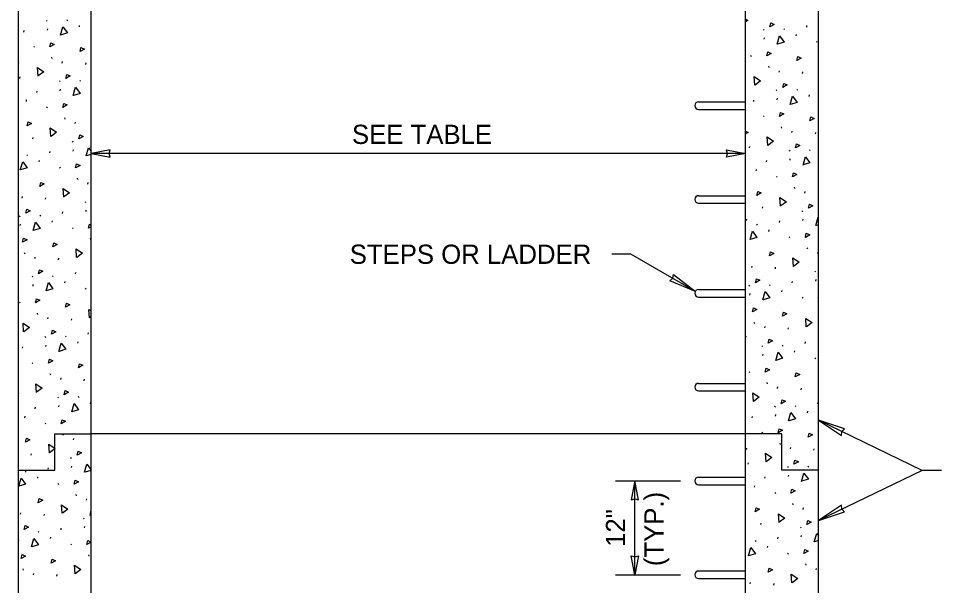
# Model space of a CAD drawing. Extents: x 99862 to 103151, y 100000 to 102076.
# Drawn here: x 100604 to 101372, y 101023 to 101495 of the extents above; entities that cross this region are included whole.
import ezdxf

# ---------------------------------------------------------------- set-up
doc = ezdxf.new("R2010")
doc.units = 0
for name, color, linetype in [('Level 15', 7, 'Continuous'), ('Level 16', 7, 'Continuous'), ('Level 17', 7, 'Continuous'), ('Level 18', 7, 'Continuous'), ('Level 20', 7, 'Continuous')]:
    doc.layers.add(name, color=color, linetype=linetype)

msp = doc.modelspace()

# ---------------------------------------------------------------- linework, layer by layer
at = {"layer": 'Level 15'}
for p, q in [((101209.03, 101382.81), (100664.59, 101382.81)), ((101113.68, 101299.02), (101097.68, 101299.02)), ((101167.26, 101268.08), (101113.68, 101299.02)), ((101355.84, 101119.04), (101269.59, 101160.87)), ((101355.84, 101119.04), (101269.59, 101077.42)), ((101372.07, 101119.14), (101356.07, 101119.14)), ((101100.85, 101110.31), (101154.85, 101110.31)), ((101116.85, 101032.25), (101116.85, 101110.33)), ((101100.85, 101032.23), (101154.85, 101032.23))]:
    msp.add_line(p, q, dxfattribs=at)
for points in [[(100664.59, 101382.81), (100680.32, 101379.73), (100679.59, 101382.81), (100680.32, 101385.89)], [(101209.03, 101382.81), (101193.3, 101379.73), (101194.03, 101382.81), (101193.3, 101385.89)], [(101167.26, 101268.08), (101146, 101276.91), (101148.41, 101278.97), (101148.98, 101282.08)], [(101269.59, 101160.87), (101288.83, 101148.22), (101289.18, 101151.37), (101291.44, 101153.59)], [(101116.85, 101110.33), (101113.76, 101094.6), (101116.85, 101095.33), (101119.93, 101094.6)], [(101269.59, 101077.42), (101291.45, 101084.65), (101289.2, 101086.88), (101288.86, 101090.03)], [(101116.85, 101032.25), (101113.76, 101047.98), (101116.85, 101047.25), (101119.93, 101047.98)]]:
    msp.add_lwpolyline(points, close=True, dxfattribs=at)
at = {"layer": 'Level 16'}
for p, q in [((100627.44, 101493.7), (100628.08, 101493.08)), ((100644.48, 101494.09), (100645.12, 101493.46)), ((100608.71, 101484), (100608.96, 101485.2)), ((100628.22, 101485.49), (100628.48, 101486.69)), ((100654.77, 101488.21), (100655.02, 101489.41)), ((101223.82, 101486.19), (101224.46, 101485.56)), ((101240.86, 101486.58), (101241.5, 101485.95)), ((101259.87, 101488.13), (101260.12, 101489.33)), ((101224.6, 101477.98), (101224.86, 101479.18)), ((101251.15, 101480.7), (101251.4, 101481.9)), ((100616.85, 101472.02), (100617.49, 101471.39)), ((101268.01, 101476.15), (101268.65, 101475.52)), ((100631.62, 101462.97), (100631.98, 101461.9)), ((101213.23, 101464.51), (101213.87, 101463.88)), ((100640.58, 101458.12), (100640.83, 101459.32)), ((100660.12, 101457.07), (100660.38, 101458.27)), ((101228, 101455.46), (101228.36, 101454.39)), ((100605.34, 101445.42), (100605.6, 101446.62)), ((101236.96, 101450.61), (101237.21, 101451.81)), ((101256.5, 101449.56), (101256.76, 101450.75)), ((100638.14, 101443.37), (100638.78, 101442.75)), ((100655.17, 101443.76), (100655.81, 101443.13)), ((100619.41, 101433.67), (100619.66, 101434.87)), ((100638.92, 101435.16), (100639.17, 101436.36)), ((101234.52, 101435.86), (101235.16, 101435.24)), ((101251.56, 101436.25), (101252.2, 101435.62)), ((101261.85, 101430.37), (101262.1, 101431.57)), ((100610.69, 101426.24), (100610.94, 101427.44)), ((101215.79, 101426.16), (101216.04, 101427.36)), ((101235.3, 101427.65), (101235.56, 101428.85)), ((100627.55, 101421.69), (100628.19, 101421.06)), ((100642.32, 101412.64), (100642.67, 101411.57)), ((100651.27, 101407.79), (100651.53, 101408.99)), ((101223.93, 101414.18), (101224.57, 101413.55)), ((101238.7, 101405.13), (101239.06, 101404.06)), ((101247.66, 101400.28), (101247.91, 101401.48)), ((100616.04, 101395.1), (100616.3, 101396.29)), ((100648.84, 101393.04), (100649.47, 101392.42)), ((101267.2, 101399.23), (101267.45, 101400.43)), ((100649.61, 101384.84), (100649.87, 101386.04)), ((101212.42, 101387.58), (101212.68, 101388.78)), ((101245.22, 101385.53), (101245.86, 101384.91)), ((101262.25, 101385.92), (101262.89, 101385.3)), ((100611.09, 101381.79), (100611.73, 101381.16)), ((100630.1, 101383.34), (100630.36, 101384.54)), ((101246, 101377.32), (101246.25, 101378.52)), ((100621.39, 101375.91), (100621.64, 101377.11)), ((100638.24, 101371.36), (100638.88, 101370.74)), ((101226.48, 101375.83), (101226.74, 101377.03)), ((100653.02, 101362.31), (100653.37, 101361.24)), ((101217.77, 101368.4), (101218.02, 101369.6)), ((101234.63, 101363.85), (101235.27, 101363.23)), ((100661.97, 101357.47), (100662.22, 101358.67)), ((101249.4, 101354.8), (101249.75, 101353.73)), ((100607.2, 101345.82), (100607.45, 101347.02)), ((101258.35, 101349.96), (101258.61, 101351.15)), ((100626.74, 101344.77), (100626.99, 101345.97)), ((100659.53, 101342.72), (100660.17, 101342.09)), ((100621.79, 101331.46), (100622.43, 101330.84)), ((100640.8, 101333.01), (100641.06, 101334.21)), ((100660.31, 101334.51), (100660.57, 101335.71)), ((101223.12, 101337.26), (101223.38, 101338.46)), ((101255.91, 101335.21), (101256.55, 101334.58)), ((100604.76, 101331.07), (100605.4, 101330.45)), ((100605.54, 101322.86), (100605.79, 101324.06)), ((100632.09, 101325.58), (100632.34, 101326.78)), ((101218.17, 101323.95), (101218.81, 101323.33)), ((101237.18, 101325.5), (101237.44, 101326.7)), ((101256.69, 101327), (101256.95, 101328.2)), ((100648.94, 101321.03), (100649.58, 101320.41)), ((101228.47, 101318.07), (101228.72, 101319.27)), ((100663.71, 101311.98), (100664.07, 101310.91)), ((101245.32, 101313.52), (101245.96, 101312.9)), ((101260.1, 101304.47), (101260.45, 101303.4)), ((101269.05, 101299.63), (101269.3, 101300.83)), ((100608.94, 101300.34), (100609.29, 101299.27)), ((100617.89, 101295.5), (100618.14, 101296.69)), ((100637.44, 101294.44), (100637.69, 101295.64)), ((101214.27, 101287.98), (101214.53, 101289.18)), ((101233.82, 101286.93), (101234.07, 101288.13)), ((100615.45, 101280.75), (100616.09, 101280.12)), ((100632.49, 101281.13), (100633.13, 101280.51)), ((100651.5, 101282.69), (100651.75, 101283.89)), ((101266.61, 101284.88), (101267.25, 101284.25)), ((101267.39, 101276.67), (101267.65, 101277.87)), ((100616.23, 101272.54), (100616.49, 101273.74)), ((100642.78, 101275.26), (100643.04, 101276.46)), ((100659.64, 101270.71), (100660.28, 101270.08)), ((101211.84, 101273.24), (101212.48, 101272.61)), ((101228.87, 101273.62), (101229.51, 101273)), ((101247.88, 101275.18), (101248.14, 101276.38)), ((101212.62, 101265.03), (101212.87, 101266.23)), ((101239.17, 101267.75), (101239.42, 101268.94)), ((101256.02, 101263.19), (101256.66, 101262.57)), ((100604.86, 101259.06), (100605.5, 101258.44)), ((100619.64, 101250.01), (100619.99, 101248.94)), ((100628.59, 101245.17), (100628.84, 101246.37)), ((100648.13, 101244.11), (100648.39, 101245.31)), ((101216.02, 101242.5), (101216.37, 101241.43)), ((100662.2, 101232.36), (100662.45, 101233.56)), ((101224.97, 101237.66), (101225.22, 101238.86)), ((101244.51, 101236.6), (101244.77, 101237.8)), ((100626.15, 101230.42), (100626.79, 101229.79)), ((100643.19, 101230.81), (100643.83, 101230.18)), ((100653.48, 101224.93), (100653.73, 101226.13)), ((101258.58, 101224.85), (101258.83, 101226.05)), ((100607.42, 101220.72), (100607.68, 101221.92)), ((100626.93, 101222.21), (100627.19, 101223.41)), ((101222.53, 101222.91), (101223.17, 101222.28)), ((101239.57, 101223.29), (101240.21, 101222.67)), ((101249.86, 101217.42), (101250.12, 101218.62)), ((100615.56, 101208.73), (100616.2, 101208.11)), ((101223.31, 101214.7), (101223.57, 101215.9)), ((101266.72, 101212.87), (101267.36, 101212.24)), ((101211.94, 101201.22), (101212.58, 101200.6)), ((100630.33, 101199.68), (100630.69, 101198.61)), ((100639.29, 101194.84), (100639.54, 101196.04)), ((100658.83, 101193.78), (100659.09, 101194.98)), ((101226.71, 101192.17), (101227.07, 101191.1)), ((101235.67, 101187.33), (101235.92, 101188.53)), ((101255.21, 101186.27), (101255.47, 101187.47)), ((100604.12, 101182.45), (100604.31, 101183.34)), ((100636.85, 101180.09), (100637.49, 101179.47)), ((100653.88, 101180.48), (100654.52, 101179.85)), ((100618.12, 101170.39), (100618.37, 101171.59)), ((100637.63, 101171.88), (100637.88, 101173.08)), ((100664.18, 101174.6), (100664.43, 101175.8)), ((101233.23, 101172.58), (101233.87, 101171.96)), ((101250.27, 101172.97), (101250.91, 101172.34)), ((101269.27, 101174.52), (101269.53, 101175.72)), ((100609.4, 101162.96), (100609.66, 101164.16)), ((101214.5, 101162.88), (101214.75, 101164.08)), ((101234.01, 101164.37), (101234.27, 101165.57)), ((101260.56, 101167.09), (101260.81, 101168.29)), ((100626.26, 101158.41), (100626.9, 101157.78)), ((100641.03, 101149.36), (100641.38, 101148.29)), ((101222.64, 101150.9), (101223.28, 101150.27)), ((100649.98, 101144.51), (100650.24, 101145.71)), ((101237.41, 101141.85), (101237.77, 101140.78)), ((100614.75, 101131.81), (100615.01, 101133.01)), ((101246.37, 101137), (101246.62, 101138.2)), ((101265.91, 101135.95), (101266.17, 101137.15)), ((100647.55, 101129.76), (100648.19, 101129.14)), ((100664.58, 101130.15), (100664.59, 101130.14)), ((101211.13, 101124.3), (101211.39, 101125.5)), ((100609.81, 101118.51), (100610.45, 101117.88)), ((100628.81, 101120.06), (100629.07, 101121.26)), ((100648.33, 101121.55), (100648.58, 101122.75)), ((101243.93, 101122.25), (101244.57, 101121.63)), ((101260.96, 101122.64), (101261.6, 101122.01)), ((100620.1, 101112.63), (100620.35, 101113.83)), ((101225.2, 101112.55), (101225.45, 101113.75)), ((101244.71, 101114.04), (101244.96, 101115.24)), ((100636.96, 101108.08), (100637.59, 101107.46)), ((101216.48, 101105.12), (101216.73, 101106.32)), ((100651.73, 101099.03), (100652.08, 101097.96)), ((100660.68, 101094.19), (100660.93, 101095.38)), ((101233.34, 101100.57), (101233.98, 101099.94)), ((101248.11, 101091.52), (101248.46, 101090.45)), ((101257.06, 101086.67), (101257.32, 101087.87)), ((100605.91, 101082.54), (100606.16, 101083.74)), ((100625.45, 101081.49), (100625.7, 101082.69)), ((100658.24, 101079.44), (100658.88, 101078.81)), ((100639.51, 101069.73), (100639.77, 101070.93)), ((100659.02, 101071.23), (100659.28, 101072.43)), ((101221.83, 101073.98), (101222.09, 101075.17)), ((101254.63, 101071.93), (101255.27, 101071.3)), ((100620.5, 101068.18), (100621.14, 101067.55)), ((100630.8, 101062.3), (100631.05, 101063.5)), ((101235.89, 101062.22), (101236.15, 101063.42)), ((101255.41, 101063.72), (101255.66, 101064.92)), ((100604.25, 101059.58), (100604.5, 101060.78)), ((100647.65, 101057.75), (100648.29, 101057.13)), ((101216.89, 101060.67), (101217.53, 101060.04)), ((101227.18, 101054.79), (101227.43, 101055.99)), ((100662.43, 101048.7), (100662.78, 101047.63)), ((101244.03, 101050.24), (101244.67, 101049.62)), ((101258.81, 101041.19), (101259.16, 101040.12)), ((100607.65, 101037.06), (100608, 101035.99)), ((100616.6, 101032.21), (100616.86, 101033.41)), ((100636.15, 101031.16), (100636.4, 101032.36)), ((101267.76, 101036.35), (101268.01, 101037.55)), ((101212.99, 101024.7), (101213.24, 101025.9)), ((101232.53, 101023.65), (101232.78, 101024.85))]:
    msp.add_line(p, q, dxfattribs=at)
for points in [[(101209.09, 101494.92), (101210.89, 101493.71), (101209.09, 101492.36)], [(100639.05, 101481.44), (100641.02, 101488.34), (100644.78, 101483.17), (100639.17, 101481.47)], [(101229.22, 101488.22), (101230.03, 101491.57), (101232.85, 101490.27), (101229.22, 101488.22)], [(101235.43, 101473.93), (101237.4, 101480.83), (101241.17, 101475.66), (101235.55, 101473.96)], [(100630.29, 101471.57), (100631.1, 101474.92), (100633.92, 101473.61), (100630.29, 101471.57)], [(100655.32, 101467.8), (100656.13, 101471.15), (100658.95, 101469.85), (100655.32, 101467.8)], [(101226.67, 101464.06), (101227.48, 101467.41), (101230.3, 101466.1), (101226.67, 101464.06)], [(101251.7, 101460.29), (101252.52, 101463.64), (101255.33, 101462.34), (101251.7, 101460.29)], [(100604.12, 101458.23), (100604.18, 101458.2), (100604.12, 101458.17)], [(100620.4, 101447.31), (100619.89, 101454.47), (100625.2, 101450.89), (100620.51, 101447.38)], [(100643.53, 101445.41), (100644.35, 101448.76), (100647.17, 101447.45), (100643.53, 101445.41)], [(101216.79, 101439.8), (101216.27, 101446.95), (101221.59, 101443.38), (101216.89, 101439.86)], [(101239.91, 101437.9), (101240.73, 101441.25), (101243.55, 101439.94), (101239.91, 101437.9)], [(100649.75, 101431.11), (100651.71, 101438.01), (100655.48, 101432.84), (100649.87, 101431.14)], [(100640.99, 101421.24), (100641.8, 101424.59), (100644.62, 101423.29), (100640.99, 101421.24)], [(101246.13, 101423.6), (101248.1, 101430.5), (101251.86, 101425.33), (101246.25, 101423.63)], [(101237.37, 101413.73), (101238.18, 101417.08), (101241, 101415.77), (101237.37, 101413.73)], [(100611.24, 101405.83), (100612.06, 101409.18), (100614.87, 101407.88), (100611.24, 101405.83)], [(101262.4, 101409.96), (101263.21, 101413.31), (101266.03, 101412.01), (101262.4, 101409.96)], [(100631.1, 101396.98), (100630.59, 101404.14), (100635.9, 101400.56), (100631.21, 101397.05)], [(101209.09, 101401.37), (101211.26, 101400.37), (101209.09, 101399.14)], [(100654.23, 101395.08), (100655.04, 101398.43), (100657.86, 101397.12), (100654.23, 101395.08)], [(101227.48, 101389.47), (101226.97, 101396.63), (101232.28, 101393.05), (101227.59, 101389.54)], [(100660.45, 101380.79), (100662.41, 101387.68), (100664.59, 101384.69)], [(101250.61, 101387.57), (101251.43, 101390.92), (101254.25, 101389.61), (101250.61, 101387.57)], [(100664.59, 101382.03), (100660.57, 101380.81)], [(101256.83, 101373.28), (101258.79, 101380.17), (101262.56, 101375), (101256.95, 101373.3)], [(100605.67, 101369.14), (100607.63, 101376.04), (100611.4, 101370.87), (100605.79, 101369.17)], [(100651.69, 101370.91), (100652.5, 101374.26), (100655.32, 101372.96), (100651.69, 101370.91)], [(101248.07, 101363.4), (101248.88, 101366.75), (101251.7, 101365.45), (101248.07, 101363.4)], [(100621.94, 101355.5), (100622.75, 101358.86), (100625.57, 101357.55), (100621.94, 101355.5)], [(100641.8, 101346.66), (100641.29, 101353.81), (100646.6, 101350.24), (100641.91, 101346.72)], [(101218.32, 101347.99), (101219.14, 101351.34), (101221.95, 101350.04), (101218.32, 101347.99)], [(101238.18, 101339.15), (101237.67, 101346.3), (101242.98, 101342.73), (101238.29, 101339.21)], [(101261.31, 101337.24), (101262.12, 101340.59), (101264.94, 101339.28), (101261.31, 101337.24)], [(100610.15, 101333.11), (100610.96, 101336.46), (100613.79, 101335.15), (100610.15, 101333.11)], [(100616.37, 101318.82), (100618.33, 101325.71), (100622.1, 101320.54), (100616.49, 101318.84)], [(100662.38, 101320.59), (100663.19, 101323.94), (100664.59, 101323.29)], [(101209.08, 101328.14), (101210.17, 101327.64), (101209.08, 101327.03)], [(101267.52, 101322.95), (101269.49, 101329.84), (101269.59, 101329.7)], [(100664.59, 101321.83), (100662.38, 101320.59)], [(101212.75, 101311.31), (101214.71, 101318.2), (101218.48, 101313.03), (101212.87, 101311.33)], [(101258.77, 101313.08), (101259.58, 101316.43), (101262.4, 101315.12), (101258.77, 101313.08)], [(101269.59, 101323.56), (101267.65, 101322.97)], [(100607.61, 101308.94), (100608.42, 101312.29), (100611.24, 101310.99), (100607.61, 101308.94)], [(100632.64, 101305.18), (100633.45, 101308.53), (100636.27, 101307.22), (100632.64, 101305.18)], [(100652.5, 101296.33), (100651.99, 101303.48), (100657.3, 101299.91), (100652.6, 101296.39)], [(101229.02, 101297.67), (101229.83, 101301.02), (101232.65, 101299.71), (101229.02, 101297.67)], [(101248.88, 101288.82), (101248.37, 101295.97), (101253.68, 101292.4), (101248.99, 101288.88)], [(100620.85, 101282.78), (100621.66, 101286.13), (100624.48, 101284.82), (100620.85, 101282.78)], [(101217.23, 101275.27), (101218.04, 101278.62), (101220.87, 101277.31), (101217.23, 101275.27)], [(100627.06, 101268.49), (100629.03, 101275.38), (100632.8, 101270.21), (100627.19, 101268.51)], [(101223.45, 101260.98), (101225.41, 101267.87), (101229.18, 101262.7), (101223.57, 101261)], [(101269.46, 101262.75), (101269.59, 101263.28)], [(101269.59, 101262.82), (101269.46, 101262.75)], [(100618.31, 101258.62), (100619.11, 101261.97), (100621.94, 101260.66), (100618.31, 101258.62)], [(100643.34, 101254.85), (100644.15, 101258.2), (100646.97, 101256.89), (100643.34, 101254.85)], [(100663.19, 101246), (100662.68, 101253.15), (100664.59, 101251.87)], [(100664.59, 101247.03), (100663.3, 101246.06)], [(101214.69, 101251.1), (101215.5, 101254.45), (101218.32, 101253.15), (101214.69, 101251.1)], [(101239.72, 101247.34), (101240.53, 101250.69), (101243.35, 101249.38), (101239.72, 101247.34)], [(100608.42, 101234.36), (100607.91, 101241.51), (100613.22, 101237.94), (100608.53, 101234.42)], [(101259.57, 101238.49), (101259.06, 101245.64), (101264.38, 101242.07), (101259.68, 101238.55)], [(100631.55, 101232.45), (100632.36, 101235.8), (100635.18, 101234.5), (100631.55, 101232.45)], [(100637.76, 101218.16), (100639.73, 101225.06), (100643.5, 101219.89), (100637.88, 101218.19)], [(101209.07, 101230.78), (101209.6, 101230.43), (101209.07, 101230.03)], [(101227.93, 101224.94), (101228.74, 101228.29), (101231.56, 101226.99), (101227.93, 101224.94)], [(101234.14, 101210.65), (101236.11, 101217.55), (101239.88, 101212.38), (101234.26, 101210.68)], [(100629, 101208.29), (100629.81, 101211.64), (100632.63, 101210.33), (100629, 101208.29)], [(100654.03, 101204.52), (100654.85, 101207.87), (100657.66, 101206.57), (100654.03, 101204.52)], [(101225.38, 101200.78), (101226.19, 101204.13), (101229.02, 101202.82), (101225.38, 101200.78)], [(101250.41, 101197.01), (101251.23, 101200.36), (101254.05, 101199.05), (101250.41, 101197.01)], [(100619.11, 101184.03), (100618.6, 101191.18), (100623.91, 101187.61), (100619.22, 101184.09)], [(100642.24, 101182.13), (100643.06, 101185.48), (100645.88, 101184.17), (100642.24, 101182.13)], [(101215.5, 101176.52), (101214.99, 101183.67), (101220.3, 101180.1), (101215.61, 101176.58)], [(101238.63, 101174.61), (101239.44, 101177.96), (101242.26, 101176.66), (101238.63, 101174.61)], [(100648.46, 101167.83), (100650.42, 101174.73), (100654.19, 101169.56), (100648.58, 101167.86)], [(101244.84, 101160.32), (101246.81, 101167.22), (101250.58, 101162.05), (101244.96, 101160.35)], [(100639.7, 101157.96), (100640.51, 101161.31), (100643.33, 101160), (100639.7, 101157.96)], [(101236.08, 101150.45), (101236.89, 101153.8), (101239.71, 101152.49), (101236.08, 101150.45)], [(101261.11, 101146.68), (101261.93, 101150.03), (101264.74, 101148.73), (101261.11, 101146.68)], [(100609.95, 101142.55), (100610.77, 101145.9), (100613.58, 101144.59), (100609.95, 101142.55)], [(100629.81, 101133.7), (100629.3, 101140.86), (100634.61, 101137.28), (100629.92, 101133.77)], [(100652.94, 101131.8), (100653.75, 101135.15), (100656.58, 101133.84), (100652.94, 101131.8)], [(101209.07, 101137.5), (101209.97, 101137.08), (101209.07, 101136.58)], [(101226.19, 101126.19), (101225.68, 101133.35), (101230.99, 101129.77), (101226.3, 101126.26)], [(100659.16, 101117.51), (100661.12, 101124.4), (100664.59, 101119.64)], [(101249.32, 101124.29), (101250.14, 101127.64), (101252.96, 101126.33), (101249.32, 101124.29)], [(100664.59, 101119.14), (100659.28, 101117.53)], [(101255.54, 101109.99), (101257.5, 101116.89), (101261.27, 101111.72), (101255.66, 101110.02)], [(100604.38, 101105.86), (100606.35, 101112.76), (100610.11, 101107.59), (100604.5, 101105.89)], [(100650.4, 101107.63), (100651.21, 101110.98), (100654.03, 101109.68), (100650.4, 101107.63)], [(101246.78, 101100.12), (101247.59, 101103.47), (101250.41, 101102.17), (101246.78, 101100.12)], [(100620.65, 101092.22), (100621.46, 101095.57), (100624.28, 101094.27), (100620.65, 101092.22)], [(100640.51, 101083.37), (100640, 101090.53), (100645.31, 101086.96), (100640.62, 101083.44)], [(101217.03, 101084.71), (101217.85, 101088.06), (101220.66, 101086.76), (101217.03, 101084.71)], [(100663.64, 101081.47), (100664.45, 101084.82), (100664.59, 101084.75)], [(100664.59, 101082.01), (100663.64, 101081.47)], [(101236.89, 101075.86), (101236.38, 101083.02), (101241.69, 101079.44), (101237, 101075.93)], [(100608.86, 101069.83), (100609.68, 101073.18), (100612.5, 101071.87), (100608.86, 101069.83)], [(101260.02, 101073.96), (101260.83, 101077.31), (101263.65, 101076), (101260.02, 101073.96)], [(101266.24, 101059.67), (101268.2, 101066.56), (101269.59, 101064.66)], [(100615.08, 101055.53), (100617.04, 101062.43), (100620.81, 101057.26), (100615.2, 101055.56)], [(100661.1, 101057.31), (100661.9, 101060.65), (100664.59, 101059.41)], [(100664.59, 101059.27), (100661.1, 101057.31)], [(101211.46, 101048.02), (101213.42, 101054.92), (101217.19, 101049.75), (101211.58, 101048.05)], [(101269.59, 101060.67), (101266.36, 101059.69)], [(100606.32, 101045.66), (100607.13, 101049.01), (100609.95, 101047.71), (100606.32, 101045.66)], [(101257.48, 101049.79), (101258.29, 101053.14), (101261.11, 101051.84), (101257.48, 101049.79)], [(100631.35, 101041.9), (100632.16, 101045.25), (100634.98, 101043.94), (100631.35, 101041.9)], [(100651.21, 101033.05), (100650.7, 101040.2), (100656.01, 101036.63), (100651.32, 101033.11)], [(101227.73, 101034.38), (101228.54, 101037.74), (101231.36, 101036.43), (101227.73, 101034.38)], [(101247.59, 101025.54), (101247.08, 101032.69), (101252.39, 101029.12), (101247.7, 101025.6)]]:
    msp.add_lwpolyline(points, dxfattribs=at)
at = {"layer": 'Level 17'}
for p, q in [((100604.12, 100643.69), (100604.12, 101611.69)), ((101269.59, 100583.14), (101269.59, 101611.69)), ((100664.59, 100643.69), (100664.59, 101551.14)), ((101209.03, 100643.69), (101209.03, 101551.14)), ((100634.36, 101119.16), (100634.36, 101149.43)), ((100634.36, 101149.43), (100664.59, 101149.43)), ((101209.03, 101149.43), (100664.59, 101149.43)), ((101239.26, 101149.43), (101209.03, 101149.43)), ((101239.26, 101119.16), (101239.26, 101149.43)), ((100604.12, 101119.16), (100634.36, 101119.16)), ((101269.5, 101119.16), (101239.26, 101119.16))]:
    msp.add_line(p, q, dxfattribs=at)
at = {"layer": 'Level 18'}
for p, q in [((101169.97, 101425.84), (101209.03, 101425.84)), ((101169.97, 101419.59), (101209.03, 101419.59)), ((101169.97, 101347.74), (101209.03, 101347.74)), ((101169.97, 101341.5), (101209.03, 101341.5)), ((101169.97, 101269.65), (101209.03, 101269.65)), ((101169.97, 101263.4), (101209.03, 101263.4)), ((101169.97, 101191.55), (101209.03, 101191.55)), ((101169.97, 101185.3), (101209.03, 101185.3)), ((101169.97, 101113.45), (101209.03, 101113.45)), ((101169.97, 101107.2), (101209.03, 101107.2)), ((101169.97, 101035.36), (101209.03, 101035.36)), ((101169.97, 101029.11), (101209.03, 101029.11))]:
    msp.add_line(p, q, dxfattribs=at)
for centre in [(101169.97, 101422.72), (101169.97, 101344.62), (101169.97, 101266.52), (101169.97, 101188.43), (101169.97, 101110.33), (101169.97, 101032.23)]:
    msp.add_arc(centre, 3.12, 90, 270, dxfattribs=at)

# ---------------------------------------------------------------- texts
at = {"layer": 'Level 20'}
for s, p in [('SEE TABLE', (100881.58, 101390.81)), ('STEPS OR LADDER', (100879.72, 101291.02))]:
    msp.add_text(s, height=16, dxfattribs=at).set_placement(p)
for s, p in [('(TYP.)', (101140.85, 101039.41)), ('12"', (101108.85, 101055.42))]:
    msp.add_text(s, height=16, rotation=90, dxfattribs=at).set_placement(p)

doc.saveas('drawing.dxf')
